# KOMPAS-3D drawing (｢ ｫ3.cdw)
File: created 14.09.2016 18:11:26, last saved 24.12.2016 15:27:20.
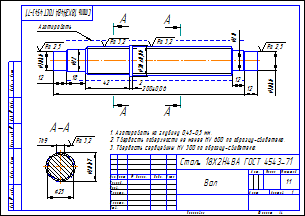
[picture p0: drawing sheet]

Sheet 1: A4, landscape

Title block, sheet 1: name: Вал; designation: Сталь 18Х2Н4ВА ГОСТ 4543-71; scale: 1:1; sheets: 1; sheet format: A4; stored path: C:\Users\nikit\OneDrive\Документы\Лабораторные\4 курс\вал.cdw

Views: Вид 2, Вид 1
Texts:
  Никита
  Лит-Масса-Масштаб
  Материал-Предприятие
  Масштаб
  Изм.
  Лист
  № докум.
  Подп.
  Дата
  Лит.
  Разраб.
  Пров.
  Т.контр.
  Листов
  Н.контр.
  Утв.
  Инв. № подл.
  Подп. и дата
  Взам. инв. №
  Инв. № дубл.
  Ra 3,2
  Ra 2,5
  1. Азотировать на глубину 0,45-0,5 мм.
  2. Твердость поверхности не менее HV 600 по образцу-свидетелю.
  3. Твердость сердцевины HV 300 по образцу-свидетелю.
  Азотировать
  Стили документа
  gliv
Dimensions and other numbers on the sheet: 1:1; 1; 7; 25; 28; 12; 18; 2; 42; 200±0,06; 22; 30±0,06; 20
